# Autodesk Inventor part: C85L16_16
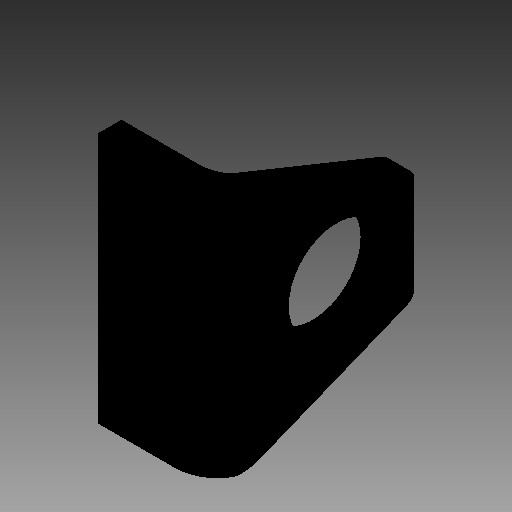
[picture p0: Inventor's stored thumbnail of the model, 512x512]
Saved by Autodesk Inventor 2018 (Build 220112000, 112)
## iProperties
Category: PARTsolutions
Company: SMC
Part Number: C85L16_16
Material: Generic
Catalog Web Link: www.cadenas.de
Description: C85 FOOT-Foot
Vendor: SMC
Document SubType Name: Modeling
Designer: partserver
Manufacturer: SMC
Mass: 5.51477 g
Surface Area: 37.2935 cm^2
Volume: 5.51477 cm^3
Density: 1 g/cm^3
Appearance: PSOLRGB-0-0-0
PSOL_IDENT_0: {$CADENAS_DATA\23d-libs\smc_jp\actuator\standard_air_cylinder\c85\accessories\c85_foot.prj},157 {VTY
PSOL_IDENT_1: P=3D},{NB=C85L16_16},{LINA=C85L16},{NN=C85 FOOT},{DATE=16.11.2020 04:36:14},{GEOMDATE=13.04.2020 02:
PSOL_IDENT_2: 43:45},{VERSION=},{LINEID=40},{WBVAR=},{WBNUMERIC=}  {NB=C85L16_16},{LINA=C85L16},{KT=DUMMY},{MODEL=
PSOL_IDENT_3: C85L16},{BORE=16},{AB=5.5},{AO=6},{AV=14},{BE=16},{LT=4.0},{NH=20},{TR=32},{UR=33},{US=42},{X1=22.00
PSOL_IDENT_4: 0},{X2=4.000},{X3=14.000},{ORDER=C85L16}
NB: C85L16_16
NN: C85 FOOT
NT: Foot
NBSYN: $MODEL._$BORE.
LINA: C85L16
CATALOG: SMC (JP
MODEL: C85L16
BORE: 16
AB: 5.5
AO: 6
AV: 14
BE: 16
LT: 4
NH: 20
TR: 32
UR: 33
US: 42
SUPPLIER: SMC
ARTICLENO: C85L16_16
BOMINFO: C85L16
CREATOR: CADENAS GmbH
Title: C85L16
Author: Cadenas PARTsolutions
Comments: Foot
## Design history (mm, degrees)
sketch "Sketch_1"
  geometry: L1 (-2, 13)-(-2, -13); L2 (5, -20)-(18, -20); L3 (18, -20)-(18, -16); L4 (18, -16)-(5, -16); L5 (2, -13)-(2, 13); L6 (2, 13)-(-2, 13); A1 r 7 centre (5, -13) between (-2, -13) and (5, -20); A2 r 3 centre (5, -13) between (2, -13) and (5, -16)
  constraints: 12 end point, 4 point on circle, 2 centre point
extrude "Extrusion1" join sketch "Sketch_1" stored distance "d0" = 42; taper "d1" = 0 deg
sketch "Sketch_2"
  geometry: C1 r 2.75 at (-12, 16); 1 further point
  constraints: 1 centre point
extrude "Extrusion2" cut sketch "Sketch_2" stored distance "d2" = 42; taper "d3" = 0 deg
sketch "Sketch_3"
  geometry: C1 r 2.75 at (-12, -16); 1 further point
  constraints: 1 centre point
extrude "Extrusion3" cut sketch "Sketch_3" stored distance "d4" = 42; taper "d5" = 0 deg
sketch "Sketch_4"
  geometry: L1 (18, 21)-(-16, 21); L2 (-16, 21)-(11.749, 9.789); L3 (13, 7.934)-(13, -7.934); L4 (11.749, -9.789)-(-16, -21); L5 (-16, -21)-(18, -21); L6 (18, -21)-(18, 21); A1 r 2 centre (11, 7.934) between (13, 7.934) and (11.749, 9.789); A2 r 2 centre (11, -7.934) between (11.749, -9.789) and (13, -7.934)
  constraints: 12 end point, 4 point on circle, 2 centre point
extrude "Extrusion4" cut sketch "Sketch_4" stored distance "d6" = 18; taper "d7" = 0 deg
sketch "Sketch_5"
  geometry: C1 r 8 at (0, 0); 1 further point
  constraints: 1 centre point
extrude "Extrusion5" cut sketch "Sketch_5" stored distance "d8" = 8; taper "d9" = 0 deg
node "Foot_Body_XY"
node "Foot_Body_YZ"
node "Foot_Body_ZX"
node "Foot_Body_X"
node "Foot_Body_Y"
node "Foot_Body_Z"
node "Foot_Body_Center"
node "UR_1_XY"
node "UR_1_YZ"
node "UR_1_ZX"
node "UR_1_X"
node "UR_1_Y"
node "UR_1_Z"
node "UR_1_Center"
node "UR_2_XY"
node "UR_2_YZ"
node "UR_2_ZX"
node "UR_2_X"
node "UR_2_Y"
node "UR_2_Z"
node "UR_2_Center"
body "Solid1"
other parameters: "d10" = 0
